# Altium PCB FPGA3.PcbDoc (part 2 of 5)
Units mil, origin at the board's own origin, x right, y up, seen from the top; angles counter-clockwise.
Board outline 4000 x 2750 mil, 12 copper layers (Top Layer, Plane1, MidLayer1, Plane2, MidLayer2, Plane3, Plane4, MidLayer 3, Plane5, MidLayer 4, Plane6, Bottom Layer), stack 57.29 mil thick; 420 components, 368 nets, 1889 pads, 1236 vias.
Unrouted connection lines stored in the file: 1.
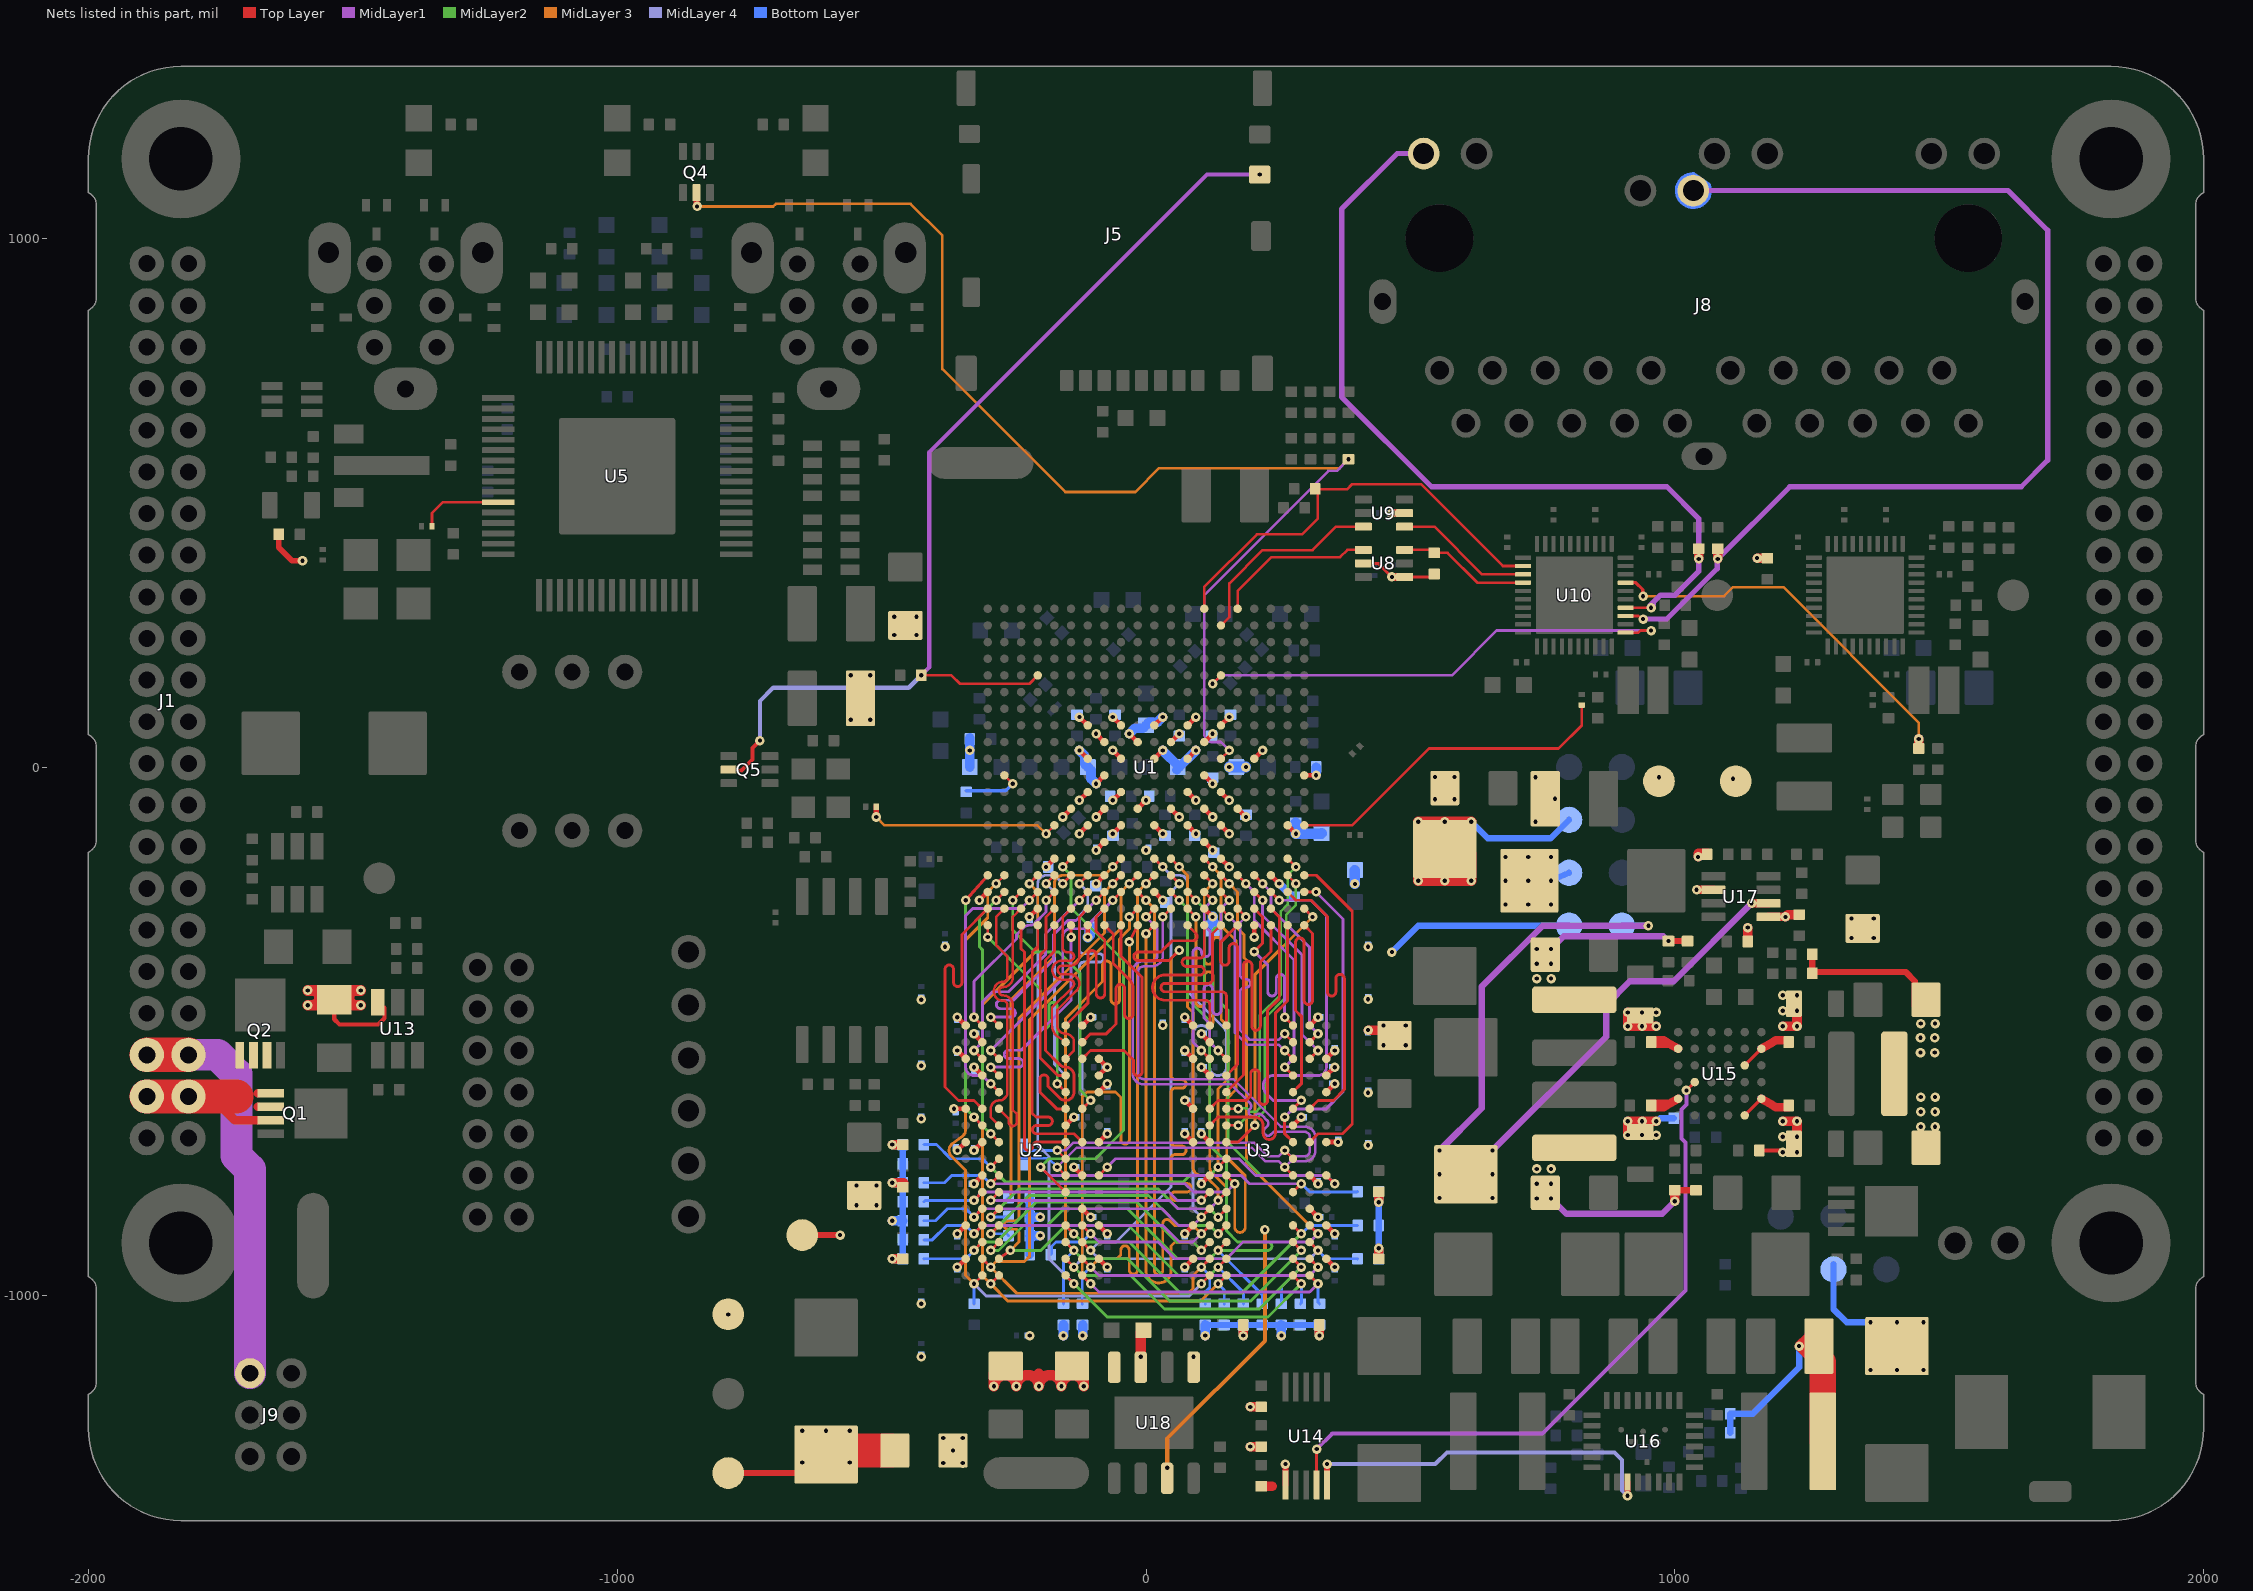
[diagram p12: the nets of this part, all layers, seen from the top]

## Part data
C1 C2 C3 C4 C5 C10 C21 C23 C24: library part CAP
C6 C7 C8 C9 C11 C12 C13 C14 C15 C16 C17 C18 C19 C20 C22 C25 C26 C27 C28 C29 C30 C31 C32 C33 C34 C35 C36 C37 C38 C39 C40 C41 C42 C43 C44 C45 C46 C47 C48 C49 C50 C51 C52 C53 C54 C55 C56 C57 C58 C59 C60 C61 C62 C63 C64 C65 C66 C67 C77 C78 CB1 CB2 CB3 CB4 CB5 CB6 CB7 CB8 CB9 CB10 CB11 CB12 CB13 CB14 CB15 CB16 CB17 CB18 CB19 CB20 CB21 CB22 CB23 CB24 CB25 CB26 CB27 CB28 CB29 CB30 CB31 CB32 CB33 CB34 CB35 CB36 CB37 CB38 CB39 CB40 CB41 CB42 CB43 CB44 CB45 CB46 CB47 CB48 CB49 CB50 CB51 CB52 CB53 CB54 CB55 CB56 CB57 CB58 CB59 CB60 CB61 CB62 CB63 CB64 CB65 CB66 CB67 CB68 CB69 CB70 CB71 CB72 CB73 CB74 CB75 CB76 CB77 CB78 CB79 CB80 CB81 CB82 CB83 CB84 CB85 CB86 CB87 CB88 CB89 CB90 CB91 CB92 CB93 CB94 CB95 CB96 CB97 CB98 CB99 CB100 CB101 CB102 CB103 CB104 CB105 CB106 CB107 CB108 CB109 CB110 CB111 CB112 CB113 CB114 CB115 CB116 CB117 CB118 CB119 CB120 CB121 CB122 CB123 CB124 CB125 CB126 CB127 CB128 CB129 CB130 CB131 CB132 CB133 CB134 CB135 CB136 CB137 CB138 CB139 CB140: library part CAP-GND
C68 C69: library part CAP-POL-GND, Voltage=50V
C70 C71: library part CAP-POL-GND, Voltage=10V
C72 C73: library part CAP-POL-GND, Volts=6.3V
C74 C75 C76: library part CAP-POL-GND, Voltage=2.5V
D1: library part TVS-GND
D2 D3 D4: Color=GREEN
D5 D6 D7 D8 D9 D10 D11 D12: library part DIODE-2/SER
J5: library part CONN-MICROSD-ST12S0
J8: "PULSE JXD0-2015NL"
L1 L2 L3 L4 L5 L6 L7 L8 L11 L12 L13 L14 L15 L16: library part INDUCTOR
M1 M2 M3 M4: "Mounting Hole"
Q1 Q2: library part MOSFET-N-PPACK
Q3: library part MOSFET-P-PPACK
Q4 Q5: library part MOSFET-N-DUAL6
Q6: library part PNP-SM
R1 R2 R3 R4 R5 R6 R7 R8 R9 R10 R11 R12 R13 R14 R15 R16 R17 R18 R19 R20 R21 R22 R23 R24 R25 R26 R27 R28 R29 R30 R31 R32 R34 R35 R38 R39 R41 R43 R46 R47 R48 R49 R50 R51 R52 R53 R54 R55 R60 R61 R62 R63 R64 R67 R68 R69 R70 R71 R72 R74 R78 R80 R84 R85 R86 R87 R88 R89 R90 R91 R94 R95 R98 R100 R102 R103 R104 R107 R108: library part R
R33 R40 R42 R44 R45 R58 R59 R60A R65 R66 R73 R75 R76 R77 R81 R82 R83 R92 R96 R97 R99 R101 R105 R106: library part R-GND
R36 R37 R56 R57 R79 R93 R109 R110 R111 R112 R113 R114 R115 R116: library part R-MINI
R117: library part R, Power=1/4W
R118: library part R, Package=1206, Power=1/4W
RN1 RN2: library part RN-DISC-SM-4X
U5: "IEEE 1394a-2000 Two-port Transceiver/Arbiter"
U6: library part TLVH431-SC70
U7: library part OSCILATOR, Freq=24.576MHz
U9: library part 2G17-1, "NC7WZ17"
U10 U11: "Ethernet PHY"
U17: library part LTC2908-B1-SOT
U19 U20: library part OSCILATOR

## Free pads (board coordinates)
  oval 60x200 smd paste-99999: 0(-1575,-905)
  round 60 smd paste-99999: 0(-1450,-210) 0(-790,-1335) 0(-790,-1185) 0(-790,-1035) 0(-650,-885) 0(970,-27) 0(1080,325) 0(1115,-27) 0(1640,325)
  oval 200x60 smd paste-99999: 0(-312.5,575) 0(-207.5,-1335)
  rrect50% 80x40 smd paste-100: 0(1710,-1370)

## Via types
v1: diameter 18, hole 8, Top Layer to Bottom Layer, tented both sides, 1236 vias

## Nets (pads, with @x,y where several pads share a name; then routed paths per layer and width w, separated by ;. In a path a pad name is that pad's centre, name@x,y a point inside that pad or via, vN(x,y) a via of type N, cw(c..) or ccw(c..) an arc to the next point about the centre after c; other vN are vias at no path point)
0.75V: C48.1 C49.1 C51.1 CB1.1 CB2.1 CB3.1 CB4.1 CB5.1 CB6.1 CB7.1 CB8.1 CB9.1 CB10.1 CB11.1 CB12.1 CB63.1 CB64.1 CB65.1 CB66.1 CB67.1 CB68.1 CB69.1 CB77.1 CB109.1 CB110.1 CB111.1 CB112.1 CB113.1 CB114.1 CB115.1 pad.0@-650,-885 R10.2 R11.2 R12.2 R13.2 R14.2 R15.2 R16.2 R17.2 R18.2 R19.2 R20.2 R21.2 R22.2 R23.2 R24.2 R25.2 R26.2 R27.2 R28.2 R29.2 R30.2 R31.2 R32.2 TP14.1 U1.H6 U1.P6 U2.H1 U2.M8 U3.H1 U3.M8 U18.3 U18.8 | length 2504.5
  Top Layer w9: v1(-356.68,-724.95) U2.H1@-340.98,-709.25 U2.H1@-340.94,-709.2 ; U2.M8@-120.51,-835.24 v1(-104.76,-850.98) ; v1(-94.49,-157.48) U1.H6@-78.74,-141.73 ; v1(73.27,-693.5) U3.H1@89.02,-709.25 ; U1.P6@110.24,-141.73 v1(125.98,-157.48) ; U3.M8@309.49,-835.24 v1(325.24,-850.98)
  Top Layer w12: pad.0@-650,-885 v1(-578.51,-885)
  Top Layer w18: v1(-480,-929.97) CB111.1@-460,-930 ; v1(-480,-785.97) CB109.1@-458,-785.97 ; v1(-480,-713.97) CB110.1@-460,-714 ; v1(183.97,-1074.97) CB115.1@184,-1055 ; v1(327.97,-1074.97) CB114.1@328,-1055 ; v1(420,-497.5) C51.1@449,-497.5 ; CB112.1@440,-930.04 v1(440.03,-910.04) ; v1@440,-822.91 CB113.1@440,-802.91
  Top Layer w20: C48.1@-287.5,-1147 v1@-287.5,-1170.93 ; -202.5,-1147 v1@-202.5,-1170.93 ; C49.1@-117.5,-1147 v1(-117.5,-1171) ccw(c-138.75,-1171) v1(-160,-1171) ccw(c-181.25,-1171) v1@-202.5,-1170.93 ; v1@-287.5,-1170.93 cw(c-266.25,-1171) v1(-245,-1171) cw(c-223.75,-1171) v1@-202.5,-1170.93 ; v1@-287.5,-1170.93 ccw(c-266.25,-1171) v1(-287.5,-1171) v1@-287.5,-1170.93 ; v1(-202.5,-1171) ccw(c-223.75,-1171) v1@-202.5,-1170.93 ; v1(-202.5,-1171) cw(c-181.25,-1171) v1@-202.5,-1170.93 ; v1(-202.5,-1171) v1@-202.5,-1170.93
  MidLayer 3 w8: v1(40,-1325) 40,-1270 225,-1085 v1(225,-875)
  Bottom Layer w12: R32.2@-460,-930 R31.2@-460,-894 R30.2@-460,-858 R29.2@-460,-822 R28.2@-460,-786 R27.2@-460,-750 R26.2@-460,-714 ; R19.2@112,-1055 R14.2@292,-1055 R13.2@328,-1055 ; v1(440.03,-910.04) v1(439.97,-822.97) ; v1(465,-350) 515,-300 TP14.1@800,-300
  Bottom Layer w16: R25.2@-220,-922 R24.2@-220,-886 -220,-850.98 R23.2@-220,-850 R22.2@-220,-814
  Bottom Layer w18: v1(-480,-929.97) R32.2@-460,-930 ; v1(-480,-857.97) R30.2@-460,-858 ; v1(-480,-785.97) R28.2@-460,-786 ; v1(-480,-713.97) R26.2@-460,-714 ; R24.2@-220,-886 v1(-200.04,-886.04) ; R23.2@-220,-850.98 v1(-200.04,-850.98) ; v1(-156.03,-1074.97) R21.2@-156,-1055 ; v1(-120.03,-1074.97) R20.2@-120,-1055 ; v1(111.97,-1074.97) R19.2@112,-1055 ; v1(183.97,-1074.97) R17.2@184,-1055 ; v1(255.97,-1074.97) R15.2@256,-1055 ; v1(327.97,-1074.97) R13.2@328,-1055 ; R12.2@440,-930 v1(440.03,-910.04) ; v1(439.97,-822.97) R10.2@440,-803
  other v1: -425,-1115 -220,-1075 -425,-1015 420,-715 -425,-665 420,-616 -425,-565 449,-526 491,-526 449,-489 491,-489 31.5,-488.19 -425,-440 420,-439 -380,-340 420,-340 0,-157.48
1.0V: C2.1 C46.1 C50.1 C52.1 C54.1 C56.1 C75.1 CB76.1 CB78.1 CB79.1 CB81.1 CB82.1 CB84.1 CB85.1 CB86.1 CB119.1 CB120.1 CB121.1 L3.2 pad.0@1115,-27 R98.1 R100.1 TP10.1 U1.G7 U1.G11 U1.G13 U1.H10 U1.H12 U1.J7 U1.J13 U1.K12 U1.L7 U1.L13 U1.M12 U1.N7 U1.N13 U1.P8 U1.P12 U1.R7 U1.R13 | length 1400.5
  Top Layer w9: v1(-125.98,-125.98) U1.G7@-110.24,-110.24 ; v1(-125.98,31.5) U1.G11@-110.24,15.75 ; v1(-125.98,94.49) U1.G13@-110.24,78.74 ; v1(-94.49,-31.5) U1.H10@-78.74,-15.75 ; v1(-94.49,62.99) U1.H12@-78.74,47.24 ; v1(-62.99,-125.98) U1.J7@-47.24,-110.24 ; v1(-62.99,94.49) U1.J13@-47.24,78.74 ; v1(-31.5,62.99) U1.K12@-15.75,47.24 ; U1.L7@15.75,-110.24 v1(31.5,-125.98) ; U1.L13@15.75,78.74 v1(31.5,94.49) ; U1.M12@47.24,47.24 v1(62.99,62.99) ; U1.N7@78.74,-110.24 v1(94.49,-125.98) ; U1.N13@78.74,78.74 v1(94.49,94.49) ; U1.P8@110.24,-78.74 v1(125.98,-94.49) ; U1.P12@110.24,47.24 v1(125.98,62.99) ; U1.R7@141.73,-110.24 v1(157.48,-125.98) ; U1.R13@141.73,78.74 v1(157.48,94.49)
  Top Layer w12: C2.1@1257.38,-387.65 C2.1@1259.88,-387.65 ; C2.1@1259.88,-390.15 C2.1@1259.88,-387.65 ; R100.1@1259.88,-354.15 C2.1@1259.88,-387.65 ; C54.1@1453.88,-450.15 1453.88,-405.15 1436.38,-387.65 C2.1@1259.88,-387.65
  Top Layer w18: v1(1044,-170) v1@1044,-167 ; R98.1@1061,-167 v1@1044,-167 ; R98.1@1061,-163 1044,-163 1044,-165 v1@1044,-167
  Top Layer w20: C75.1@515,-165 v1(515,-215) v1(565,-215) v1(615,-215) C75.1@615,-165 ; v1(515,-103.5) v1(565,-103.5) v1(615,-103.5)
  Bottom Layer w12: v1(615,-103.5) 646.5,-135 765,-135 TP10.1@800,-100
  Bottom Layer w18: v1(-125.98,31.5) -116,21.51 -116,6 CB121.1@-110,0 -104,-6 -104,-21.98 v1(-94.49,-31.5) ; v1(-31.5,62.99) -21.49,73 -6,73 CB119.1@0,79 6,85 22.01,85 v1(31.5,94.49)
  Bottom Layer w20: v1(157.48,0) v1(188.98,0)
  other v1: 1465,-680 1492,-680 1465,-652 1492,-652 1465,-624 1492,-624 1464.5,-540 1491.5,-540 1464.5,-512 1491.5,-512 1465,-485 1492,-485 1334,-323.5 1376,-323.5 1334,-286.5 1376,-286.5 546.5,-61 583.5,-61 1110,-22 546.5,-19 583.5,-19 -476,249.5 -434,249.5 -476,284 -434,284
1.2MHz_10: U14.5 U16.3 | length 710.4
  Top Layer w11: U14.5@342.37,-1357.5 v1(342.37,-1318) ; v1(910.47,-1378) U16.3@910.47,-1352
  MidLayer 4 w8: v1(342.37,-1318) 547,-1318 569,-1296 886,-1296 900.26,-1310.26 900.26,-1367.79 v1(910.47,-1378)
1.5V: C3.1 C47.1 C55.1 C76.1 CB13.1 CB14.1 CB15.1 CB16.1 CB17.1 CB18.1 CB19.1 CB20.1 CB21.1 CB22.1 CB23.1 CB24.1 CB25.1 CB26.1 CB27.1 CB28.1 CB29.1 CB30.1 CB31.1 CB32.1 CB33.1 CB34.1 CB35.1 CB36.1 CB37.1 CB38.1 CB39.1 CB40.1 CB41.1 CB42.1 CB43.1 CB44.1 CB45.1 CB46.1 CB47.1 CB48.1 CB87.1 CB95.1 CB99.1 CB103.1 CB122.1 CB133.1 L4.2 pad.0@-790,-1035 R34.1 R107.1 TP13.1 U1.A3 U1.D2 U1.E5 U1.G1 U1.H4 U1.L3 U1.P2 U1.R5 U1.U1 U1.V4 U2.A1 U2.A8 U2.B2 U2.C1 U2.C9 U2.D2 U2.D9 U2.E9 U2.F1 U2.G7 U2.H2 U2.H9 U2.K2 U2.K8 U2.N1 U2.N9 U2.R1 U2.R9 U3.A1 U3.A8 U3.B2 U3.C1 U3.C9 U3.D2 U3.D9 U3.E9 U3.F1 U3.G7 U3.H2 U3.H9 U3.K2 U3.K8 U3.N1 U3.N9 U3.R1 U3.R9 U17.2 U18.5 U18.7 | length 2996.5
  Top Layer w9: v1(-363.26,-646.26) U2.F1@-340.98,-646.26 ; v1(-356.73,-945.47) U2.R1@-340.98,-929.72 ; v1(-356.73,-882.48) U2.N1@-340.98,-866.73 ; v1(-356.73,-536.02) U2.C1@-340.98,-551.77 ; v1(-356.73,-473.03) U2.A1@-340.98,-488.78 ; v1(-325.24,-787.99) U2.K2@-309.49,-772.24 ; v1(-325.24,-725) U2.H2@-309.49,-709.25 ; v1(-325.24,-567.52) U2.D2@-309.49,-583.27 ; v1(-325.24,-504.53) U2.B2@-309.49,-520.28 ; v1(-314.96,-251.97) U1.A3@-299.21,-236.22 ; v1(-220.47,-283.46) U1.D2@-204.72,-267.72 ; v1(-188.98,-188.98) U1.E5@-173.23,-173.23 ; U2.G7@-152.01,-677.76 v1(-136.26,-662.01) ; v1(-136.26,-756.5) U2.K8@-120.51,-772.24 ; U2.A8@-120.51,-488.78 v1(-104.76,-473.03) ; v1(-110.24,-321.48) U1.G1@-110.24,-299.21 ; v1(-94.49,-220.47) U1.H4@-78.74,-204.72 ; U2.R9@-89.02,-929.72 v1(-73.27,-945.47) ; U2.N9@-89.02,-866.73 v1(-73.27,-882.48) ; U2.H9@-89.02,-709.25 v1(-73.27,-693.5) ; U2.E9@-89.02,-614.76 v1(-73.27,-599.02) ; U2.D9@-89.02,-583.27 v1(-73.27,-567.52) U2.C9@-89.02,-551.77 ; U1.L3@15.75,-236.22 v1(31.5,-251.97) ; v1(73.27,-945.47) U3.R1@89.02,-929.72 ; v1(73.27,-882.48) U3.N1@89.02,-866.73 ; v1(73.27,-630.51) U3.F1@89.02,-646.26 ; v1(73.27,-536.02) U3.C1@89.02,-551.77 ; v1(73.27,-473.03) U3.A1@89.02,-488.78 ; v1(104.76,-787.99) U3.K2@120.51,-772.24 ; v1(104.76,-693.5) U3.H2@120.51,-709.25 ; v1(104.76,-567.52) U3.D2@120.51,-583.27 ; v1(104.76,-504.53) U3.B2@120.51,-520.28 ; U1.P2@110.24,-267.72 v1(125.98,-283.46) ; U1.R5@141.73,-173.23 v1(157.48,-188.98) ; v1(204.72,-321.48) U1.U1@204.72,-299.21 ; U1.V4@236.22,-204.72 v1(251.97,-220.47) ; U3.G7@277.99,-677.76 v1(293.74,-662.01) ; U3.K8@309.49,-772.24 v1(325.24,-787.99) ; U3.A8@309.49,-488.78 v1(325.24,-473.03) ; U3.R9@340.98,-929.72 v1(356.73,-945.47) ; U3.N9@340.98,-866.73 v1(356.73,-882.48) ; U3.H9@340.98,-709.25 v1(363.26,-709.25) ; U3.E9@340.98,-614.76 v1(356.73,-599.02) ; U3.D9@340.98,-583.27 v1(356.73,-567.52) ; U3.C9@340.98,-551.77 v1(356.73,-536.02)
  Top Layer w12: C3.1@1000,-800 R107.1@1040,-800
  Top Layer w16: v1(1145,-257.8) U17.2@1177,-257.8
  Top Layer w18: v1(1000,-821) C3.1@1000,-800
  Top Layer w20: U18.7@-10,-1135 v1(-10,-1115) -10,-1070 CB133.1@-5,-1065
  MidLayer1 w12: v1(555,-725) 635,-645 635,-415 750,-300 v1(950,-300) ; v1(655,-725) 870,-510 870,-450 915,-405 997.8,-405 v1(1145,-257.8) ; v1(766,-816) 795,-845 976,-845 v1(1000,-821)
  Bottom Layer w12: TP13.1@900,-300 v1(950,-300)
  Bottom Layer w15: v1(251.97,-220.47) CB95.1@277.42,-245.93
  Bottom Layer w20: v1(-110.24,-321.48) -106.61,-317.86 CB99.1@-106.61,-302.5 ; CB122.1@125.98,-303.5 v1(125.98,-283.46)
  other v1: 90,-1115 -790,-1035 -547.5,-828.5 -509.5,-828.5 739,-816 555,-815 655,-815 -547.5,-791.5 -509.5,-791.5 739,-788 766,-788 555,-770 655,-770 739,-760 766,-760
1.8V: C1.1 C53.1 C66.1 C67.1 C74.1 CB70.1 CB71.1 CB80.1 CB83.1 CB93.1 CB98.1 CB102.1 CB106.1 CB107.1 CB118.1 CB127.1 CB128.1 L5.2 L8.1 pad.0@970,-27 R62.2 R63.2 R108.1 TP12.1 U1.F8 U1.G9 U1.H8 U1.J9 U1.J11 U1.K8 U1.L11 U1.M8 U1.N9 U1.N11 U1.P10 U1.R9 U1.T8 U1.U11 U1.W7 U1.Y10 U8.1 U8.5 U9.5 U17.6 | length 1182.8
  Top Layer w5: U8.1@489,359.41 R62.2@539.41,359.41
  Top Layer w6: U8.5@411,385 439.41,385 v1(465,359.41)
  Top Layer w8: C66.1@-540,130 -540,136.5 C66.1@-516.5,160
  Top Layer w9: v1(-157.48,-94.49) U1.F8@-141.73,-78.74 ; v1(-125.98,-62.99) U1.G9@-110.24,-47.24 ; v1(-94.49,-94.49) U1.H8@-78.74,-78.74 ; v1(-62.99,-62.99) U1.J9@-47.24,-47.24 ; v1(-62.99,31.5) U1.J11@-47.24,15.75 ; U1.K8@-15.75,-78.74 v1(0,-62.99) ; U1.L11@15.75,15.75 v1(31.5,31.5) ; U1.M8@47.24,-78.74 v1(62.99,-94.49) ; U1.N9@78.74,-47.24 v1(94.49,-62.99) ; U1.N11@78.74,15.75 v1(94.49,31.5) ; U1.P10@110.24,-15.75 v1(125.98,-31.5) ; U1.R9@141.73,-47.24 v1(157.48,-62.99) ; U1.T8@173.23,-78.74 v1(188.98,-94.49) ; U1.U11@204.72,15.75 v1(220.47,31.5) ; U1.W7@267.72,-110.24 v1(283.47,-125.98) ; U1.Y10@299.21,-15.75 v1(321.48,-15.75)
  Top Layer w12: v1(988,-329) R108.1@1024,-329
  Top Layer w15: v1(465,359.41) U8.1@489,359.41 ; v1(465,480) U9.5@489,480
  Top Layer w16: v1(1041,-232.2) U17.6@1073,-232.2
  Top Layer w18: v1(1155.5,395) R63.2@1175,395
  MidLayer1 w12: v1(766,-344) 790,-320 977.97,-320 986.97,-329 v1(988,-329)
  Bottom Layer w12: v1(766,-215) TP12.1@800,-200
  Bottom Layer w18: L8.1@-333.15,0 CB102.1@-333.15,55 ; v1@31.5,31.4 CB118.1@63.32,-0.42 ; CB118.1@58.06,-4.83 94.39,31.5 v1(94.49,31.5) ; v1(321.48,-15.75) 321.48,-0.52 CB98.1@322,0
  Bottom Layer w20: CB93.1@283.46,-105 v1(283.47,-125.98) 331.02,-125.98 CB127.1@332,-125 ; v1(395,-221) CB128.1@395,-195
  other v1: 739,-400 766,-400 739,-372 766,-372 739,-344 680,-260 723,-260 766,-260 680,-215 723,-215 680,-170 723,-170 766,-170 736.5,-103.5 773.5,-60 736.5,-19.5 970,-19.5 -333.15,31.5 -558.5,89.5 -521.5,89.5 -558.5,173.5 -521.5,173.5
3.3V-OUT_2: J1.39 J1.40 J9.2 Q2.1 Q2.2 Q2.3 | length 839.8
  Top Layer w65: J1.40@-1889.37,-544.29 J1.39@-1810.63,-544.29
  MidLayer1 w60: J1.40@-1889.37,-544.29 J1.39@-1810.63,-544.29 -1755.71,-544.29 -1720,-580 -1720,-735 -1694.37,-760.63 J9.2@-1694.37,-1146.26
5V: C70.1 L16.2 pad.0@-790,-1335 R57.1 R118.1 U13.6 | length 871.9
  Top Layer w8: R118.1@-1535,-440 -1535,-477 -1525,-487 -1452,-487 -1440,-475 -1440,-455
  Top Layer w11: R57.1@-1640,440 -1640,415 -1615,390 v1(-1595,390) ; pad.0@-790,-1335 -640,-1335 C70.1@-605,-1300
  Top Layer w20: v1(-1585,-450.5) v1@-1577,-450.5 ; v1(-1585,-422.5) v1@-1577,-422.5 ; R118.1@-1540,-450.5 v1@-1577,-450.5 ; R118.1@-1540,-422.5 v1@-1577,-422.5 ; R118.1@-1530,-450.5 v1@-1493,-450.5 ; R118.1@-1530,-422.5 v1@-1493,-422.5 ; v1(-1485,-450.5) v1@-1493,-450.5 ; v1(-1485,-422.5) v1@-1493,-422.5 ; v1@-1577,-450.5 ccw(c-1577,-436.5) v1@-1577,-422.5 ; v1@-1577,-450.5 ccw(c-1577,-436.5) v1@-1577,-422.5 ; v1@-1493,-450.5 cw(c-1493,-436.5) v1@-1493,-422.5 ; v1@-1493,-450.5 cw(c-1493,-436.5) v1@-1493,-422.5
  Top Layer w65: C70.1@-557.5,-1292.5 L16.2@-482.5,-1292.5
  other v1: -650,-1315 -560,-1315 -650,-1255 -605,-1255 -560,-1255
5V-DCDC_10: C4.1 C15.1 C16.1 C17.1 C18.1 C19.1 C22.1 C42.1 C43.1 C44.1 C45.1 C65.1 C71.1 L1.2 L16.1 R9.2 R72.1 R74.1 R94.2 R95.2 R103.1 TP3.1 U14.1 U15.B1 U15.B6 U15.C5 U15.E1 U15.E6 U15.F5 U17.1 | length 1525.1
  Top Layer w6: U15.F5@1132.24,-658.74 U15.E6@1163.74,-627.24 ; U15.C5@1132.24,-564.25 U15.B6@1163.74,-532.76
  Top Layer w8: R72.1@1160,-725 1203,-725 v1@1204,-726
  Top Layer w11: U14.1@263.63,-1357.5 v1(263.63,-1318)
  Top Layer w12: U17.1@1176.43,-283.95 U17.1@1177,-283.39
  Top Layer w16: C17.1@955,-643 978.97,-643 989.36,-637 ; C17.1@955,-637 989.36,-637 ; C16.1@955,-523 989.36,-523 ; C16.1@955,-517 978.97,-517 989.36,-523 ; U15.E1@1006.26,-627.24 989.36,-637 ; U15.B1@1006.26,-532.76 989.36,-523 ; U15.E6@1163.74,-627.24 1180.64,-637 1191.03,-643 C19.1@1215,-643 ; U15.B6@1163.74,-532.76 1180.64,-523 1191.03,-517 C18.1@1215,-517 ; U17.1@1177,-283.39 v1(1209,-283.39)
  Top Layer w18: v1(197,-1285) R95.2@218,-1285 ; v1(197,-1210) R94.2@218,-1210 ; C22.1@218,-1360 239,-1360 ; v1(911,-696) v1(911,-670) v1(938,-670) v1(965,-670) ; v1(911,-464) v1(911,-490) v1(938,-490) v1(965,-490) ; R9.2@1138,-330 v1(1138,-303.5) ; v1(1204,-670) v1(1231,-670) C45.1@1231,-697 ; v1(1204,-490) v1(1231,-490) C43.1@1231,-463 ; v1(1209,-283.39) 1213.04,-279.35 1234.65,-279.35 C15.1@1235,-279 ; C65.1@1252.68,-1112.68 v1(1235,-1095) C65.1@1252.68,-1077.32
  Top Layer w50: L1.2@1280,-1275 C65.1@1280,-1125
  Bottom Layer w12: v1(965,-670) 966.62,-670 972.62,-664 R74.1@998,-664 ; R103.1@1105,-1259 C4.1@1105,-1223 1147,-1223 1235,-1135 v1(1235,-1095) ; TP3.1@1300,-940 TP3.1@1300,-950 1300,-1025 1325,-1050 v1(1370,-1050)
  other v1: -383.5,-1316 -346.5,-1316.07 -365,-1292.57 -383.5,-1269 -346.5,-1269 1370,-1140 1420,-1140 1470,-1140 1420,-1050 1470,-1050 1204,-728.5 1231,-728.5 1204,-699 1231,-699 938,-696 965,-696 938,-464 965,-464 1204,-461 1231,-461 1204,-431.5 1231,-431.5
5V-OUT_2: J1.41 J1.42 Q1.1 Q1.2 Q1.3 | length 283.2
  Top Layer w16: -1767.78,-623.03 -1723.02,-667.8 -1680,-667.8 Q1.3@-1677.5,-667.8 ; Q1.2@-1680,-642.2 Q1.2@-1677.5,-642.2 ; Q1.1@-1680,-616.61 Q1.1@-1677.5,-616.61
  Top Layer w65: J1.42@-1889.37,-623.03 J1.41@-1810.63,-623.03 -1767.78,-623.03 -1720,-623.03
/1.2MHz_10: U14.4 U15.D2 | length 1297.1
  Top Layer w6: U14.4@322.68,-1357.5 v1(322.68,-1289.68) ; v1(1022.01,-611.5) U15.D2@1037.76,-595.75
  MidLayer1 w8: v1(322.68,-1289.68) 352.37,-1260 750,-1260 1020,-990 1020,-710 1012.5,-702.5 1012.5,-647.5 1022.01,-637.99 v1(1022.01,-611.5)
/CAS_7: R28.1 U1.P5 U2.K3 U3.K3 | length 1514.1
  Top Layer w5.49: v1(-293.74,-787.99) U2.K3@-277.99,-772.24 ; U1.P5@110.24,-173.23 v1(125.98,-188.98) ; U3.K3@152.01,-772.24 v1(167.76,-787.99)
  MidLayer1 w5.49: v1(-293.74,-787.99) 73.88,-787.99 89.63,-803.74 152.01,-803.74 v1(167.76,-787.99)
  MidLayer 3 w5.49: v1(125.98,-188.98) 141.73,-204.72 141.73,-300 170,-328.27 170,-610 152.76,-627.24 152.76,-737.76 187.76,-772.76 187.76,-870 cw(c177.76,-870) 167.76,-870 v1(167.76,-787.99)
  Bottom Layer w5.49: R28.1@-420,-786 -381,-786 -367.24,-772.24 -309.49,-772.24 v1@-293.77,-787.96
/CS_7: R29.1 U1.N1 U2.L2 U3.L2 | length 1532.2
  Top Layer w5.49: v1(-325.24,-819.49) U2.L2@-309.49,-803.74 ; v1(62.99,-346.46) 43.45,-366 -15,-366 cw(c-15,-358) -15,-350 27.95,-350 49.45,-328.5 88.71,-328.5 ccw(c88.71,-320.5) 94.37,-314.84 U1.N1@78.74,-299.21 ; v1(104.76,-819.49) U3.L2@120.51,-803.74
  MidLayer1 w5.49: v1(-325.24,-819.49) -309.49,-803.74 43.74,-803.74 59.49,-819.49 v1(104.76,-819.49)
  MidLayer 3 w5.49: v1(62.99,-346.46) 47.24,-362.21 47.24,-583 ccw(c55.24,-583) 55.24,-591 67.77,-591 cw(c67.77,-599) 67.77,-607 55.24,-607 ccw(c55.24,-615) 47.24,-615 47.24,-708.8 ccw(c55.24,-708.8) 55.24,-716.8 67.77,-716.8 cw(c67.77,-724.8) 67.77,-732.8 55,-732.8 ccw(c55,-740.8) 47,-740.8 47,-779.49 ccw(c55,-779.49) 55,-787.49 77.5,-787.49 cw(c77.5,-795.49) 77.5,-803.49 55,-803.49 ccw(c55,-811.49) 55,-819.49 v1(104.76,-819.49)
  Bottom Layer w5.49: R29.1@-420,-822 -417.48,-819.49 v1(-325.24,-819.49)
/RAS_7: R26.1 U1.P4 U2.J3 U3.J3 | length 1340.1
  Top Layer w5.49: v1(-293.74,-756.5) U2.J3@-277.99,-740.75 ; U1.P4@110.24,-204.72 v1(125.98,-220.47) ; v1@136.36,-756.5 152.06,-740.8 U3.J3@152.1,-740.75
  MidLayer2 w5.49: v1(-293.74,-756.5) -265.23,-785 70,-785 82.76,-772.24 120.51,-772.24 v1(136.26,-756.5)
  MidLayer 3 w5.49: v1(125.98,-220.47) 110.24,-236.22 110.24,-365 ccw(c118.24,-365) 126.24,-365 126.24,-330 cw(c134.24,-330) 142.24,-330 142.24,-477.24 155,-490 155,-590 136.26,-608.74 136.26,-756.4 v1@136.36,-756.5
  Bottom Layer w5.49: R26.1@-420,-714 -396,-714 -369.25,-740.75 -309.49,-740.75 v1@-293.77,-756.47
/RESET_6: R55.1 U1.B10 | length 115.9
  Top Layer w5: U1.B10@-267.72,-15.75 v1(-251.97,-31.5)
  Bottom Layer w6: R55.1@-340,-45 -265.47,-45 v1(-251.97,-31.5)
/RESET_7: R75.1 U1.B4 U2.T2 U3.T2 | length 1369.9
  Top Layer w5: v1(-325.24,-976.97) U2.T2@-309.49,-961.22 ; v1(-283.46,-220.47) U1.B4@-267.72,-204.72 ; v1(104.76,-976.97) U3.T2@120.51,-961.22
  MidLayer1 w6: v1@-325.24,-980.22 v1(-325.24,-976.97)
  MidLayer 3 w5.49: v1(-325.24,-976.97) -340.98,-961.22 -340.98,-762.92 -367.82,-736.09 cw(c-356.68,-724.95) -366.38,-712.54 -347.03,-697.91 ccw(c-356.73,-685.5) -340.98,-685.5 -340.98,-326.77 -299.21,-285 -299.21,-236.22 v1(-283.46,-220.47)
  MidLayer 4 w5.49: v1(-325.24,-976.97) -302.2,-1000 81.73,-1000 v1(104.76,-976.97)
  Bottom Layer w6: v1(-325.24,-976.97) -325.24,-1014.76 R75.1@-325,-1015
/SD-CD: J5.11 Q5.5 R53.1 U1.D16 | length 2003.4
  Top Layer w5: v1(-425,173.5) -368.03,173.5 -352.01,157.48 -220.47,157.48 U1.D16@-204.72,173.23
  Top Layer w6: Q5.5@-789,-5 Q5.5@-787.5,-5
  Top Layer w8: Q5.5@-787.5,-5 -789.24,-6.74 -764.74,-6.74 -744,14 -744,36 v1(-730,50)
  MidLayer1 w8: v1(-425,173.5) -410,188.5 -410,595 115.28,1120.28 v1(215,1120.28)
  MidLayer 4 w8: v1(-730,50) -730,125 -705,150 -448.5,150 v1(-425,173.5)
/WE_7: R22.1 U1.M5 U2.L3 U3.L3 | length 1212.3
  Top Layer w5.49: v1(-293.74,-819.49) U2.L3@-277.99,-803.74 ; U1.M5@47.24,-173.23 v1(62.99,-188.98) ; v1(136.26,-819.49) U3.L3@152.01,-803.74
  MidLayer1 w5.49: v1(-293.74,-819.49) 44.49,-819.49 60.24,-835.24 120.51,-835.24 v1(136.26,-819.49)
  MidLayer 3 w5.49: v1(62.99,-188.98) 78.74,-204.72 78.74,-453.74 89.02,-464.02 89.02,-756.5 ccw(c104.76,-756.5) 104.76,-772.24 cw(c104.76,-787.99) 115.9,-776.86 136.26,-797.22 v1(136.26,-819.49)
  Bottom Layer w5: v1(-293.74,-819.49) -265.48,-819.49 R22.1@-260,-814
A0: R24.1 U1.N2 U2.N3 U3.N3 | length 1362.7
  Top Layer w5.49: v1(-293.74,-882.48) U2.N3@-277.99,-866.73 ; U1.N2@78.74,-267.72 v1(94.49,-283.46) ; v1(136.26,-882.48) U3.N3@152.01,-866.73
  MidLayer2 w5.49: v1(-293.74,-882.48) -221.26,-810 5,-810 61.73,-866.73 120.51,-866.73 v1(136.26,-882.48)
  MidLayer 3 w5.49: v1(94.49,-283.46) 94.49,-445 ccw(c102.49,-445) 110.49,-445 110.49,-395 cw(c118.49,-395) 126.49,-395 126.49,-483.51 120.51,-489.49 120.51,-756.5 ccw(c136.26,-756.5) 125.12,-767.63 152.01,-794.52 152.01,-866.73 v1(136.26,-882.48)
  Bottom Layer w5: v1(-293.74,-882.48) -263.52,-882.48 R24.1@-260,-886
A1: R21.1 U1.K2 U2.P7 U3.P7 | length 1539.5
  Top Layer w5.49: U2.P7@-152.01,-898.23 v1(-136.26,-913.98) ; v1(-31.5,-283.46) U1.K2@-15.75,-267.72 ; U3.P7@277.99,-898.23 v1(293.74,-913.98)
  MidLayer2 w5.49: v1(-136.26,-913.98) -120.51,-929.72 -35,-929.72 45.28,-1010 197.72,-1010 v1(293.74,-913.98)
  MidLayer 3 w5.49: v1(-136.26,-913.98) -152.01,-898.23 -152.01,-475.8 -82,-405.79 -82,-375 cw(c-74,-375) -66,-375 -66,-440 ccw(c-58,-440) -50,-440 -50,-325 -31.5,-306.5 v1(-31.5,-283.46)
  Bottom Layer w5.49: R21.1@-156,-1015 -156,-933.72 v1(-136.26,-913.98)
A2: R16.1 U1.M3 U2.P3 U3.P3 | length 1578.3
  Top Layer w5.49: v1(-293.74,-913.98) U2.P3@-277.99,-898.23 ; U1.M3@47.24,-236.22 v1(62.99,-251.97) ; v1(136.26,-913.98) U3.P3@152.01,-898.23
  MidLayer2 w5.49: v1(-293.74,-913.98) -278.98,-913.98 -231.73,-866.73 -186.73,-866.73 -155.24,-835.24 -34.76,-835.24 59.72,-929.72 120.51,-929.72 v1(136.26,-913.98) 230,-913.98 ccw(c230,-905.98) 230,-897.98 172.98,-897.98 152.01,-877.01 152.01,-747.01 120.51,-715.51 120.51,-480.51 78.74,-438.74 78.74,-267.72 v1(62.99,-251.97)
  Bottom Layer w5.49: v1(136.26,-913.98) 220,-997.72 R16.1@220,-1015
A3: R31.1 U1.K3 U2.N2 U3.N2 | length 1544.1
  Top Layer w5.49: v1(-325.24,-882.48) U2.N2@-309.49,-866.73 ; U1.K3@-15.75,-236.22 v1(0,-251.97) ; v1(104.76,-882.48) U3.N2@120.51,-866.73
  MidLayer1 w5.49: v1(-325.24,-882.48) -309.49,-866.73 31.73,-866.73 63.23,-898.23 89.02,-898.23 v1(104.76,-882.48)
  MidLayer 3 w5.49: v1(0,-251.97) 15.75,-267.72 15.75,-952 ccw(c23.75,-952) 31.75,-952 31.75,-863.5 cw(c39.75,-863.5) 45.4,-857.85 54.29,-866.73 89.02,-866.73 v1(104.76,-882.48)
  Bottom Layer w5.49: R31.1@-420,-894 -404,-894 -376.73,-866.73 -340.99,-866.73 v1(-325.24,-882.48)
A4: R12.1 U1.M4 U2.P8 U3.P8 | length 1373.1
  Top Layer w5.49: U2.P8@-120.51,-898.23 v1(-104.76,-913.98) ; U1.M4@47.24,-204.72 v1(62.99,-220.47) ; U3.P8@309.49,-898.23 v1(325.24,-913.98)
  MidLayer 4 w5.49: v1(62.99,-220.47) 47.24,-236.22 47.24,-794.21 -56.77,-898.23 -89.02,-898.23 v1(-104.76,-913.98) -89.02,-929.72 309.49,-929.72 v1(325.24,-913.98)
  Bottom Layer w5.49: v1@325.27,-914.01 340.98,-929.72 399.72,-929.72 R12.1@400,-930
A5: R32.1 U1.L1 U2.P2 U3.P2 | length 1498.9
  Top Layer w5.49: v1(-325.24,-913.98) U2.P2@-309.49,-898.23 ; v1(0,-314.96) U1.L1@15.75,-299.21 ; v1(104.76,-913.98) U3.P2@120.51,-898.23
  MidLayer2 w5.49: v1(-325.24,-913.98) -309.49,-898.23 -283.23,-898.23 -207.5,-822.5 -17.5,-822.5 58.22,-898.23 89.02,-898.23 v1(104.76,-913.98)
  MidLayer 3 w5.49: v1(0,-314.96) 0,-952 ccw(c23.75,-952) 47.5,-952 47.5,-905.44 54.7,-898.23 89.02,-898.23 v1(104.76,-913.98)
  Bottom Layer w5.49: R32.1@-420,-930 -419.72,-929.72 -340.98,-929.72 v1@-325.27,-914.01
A6: R20.1 U1.L4 U2.R8 U3.R8 | length 1486.4
  Top Layer w5.49: U2.R8@-120.51,-929.72 v1(-104.76,-945.47) ; v1(0,-220.47) U1.L4@15.75,-204.72 ; U3.R8@309.49,-929.72 v1(325.24,-945.47)
  MidLayer1 w5.49: v1(-104.76,-945.47) -89.02,-961.22 309.49,-961.22 v1(325.24,-945.47)
  MidLayer 3 w5.49: v1(-104.76,-945.47) -89.02,-929.72 -54.72,-929.72 -47.75,-922.75 -47.75,-913.25 cw(c-39.75,-913.25) -31.75,-913.25 -31.75,-950.75 ccw(c-23.75,-950.75) -15.75,-950.75 -15.75,-236.22 v1(0,-220.47)
  Bottom Layer w5.49: R20.1@-120.51,-1015 -120.51,-961.22 v1(-104.76,-945.47)
A7: R19.1 U1.K4 U2.R2 U3.R2 | length 1465.4
  Top Layer w5.49: U2.R2@-309.58,-929.72 v1@-293.84,-945.47 ; v1(-31.5,-220.47) U1.K4@-15.75,-204.72 ; v1(104.76,-945.47) U3.R2@120.51,-929.72
  MidLayer 3 w5.49: v1(-31.5,-220.47) -47.24,-236.22 -47.24,-304.74 -220,-477.5 -220,-925 -230,-935 -283.36,-935 -293.84,-945.47 -244.31,-995 80,-995 89.02,-985.98 89.02,-961.22 v1(104.76,-945.47)
  Bottom Layer w5.49: v1(104.76,-945.47) 120.51,-961.22 120.51,-984.49 112,-993 R19.1@112,-1015
  other v1: -293.74,-945.47
A8: R13.1 U1.K1 U2.T8 U3.T8 | length 1482.4
  Top Layer w5.49: U2.T8@-120.51,-961.22 v1(-104.76,-976.97) ; v1(-31.5,-330.71) U1.K1@-15.75,-299.21 ; U3.T8@309.49,-961.22 v1(325.24,-976.97)
  MidLayer1 w5.49: v1(-104.76,-976.97) -89.02,-992.72 309.49,-992.72 v1(325.24,-976.97)
  MidLayer 3 w5.49: v1(-104.76,-976.97) -120.51,-961.22 -120.51,-623.5 -111.77,-614.76 -57.52,-614.76 -47.5,-624.79 -47.5,-705 ccw(c-39.5,-705) -31.5,-705 v1(-31.5,-330.71)
  Bottom Layer w5.49: v1(325.24,-976.97) 325.24,-1012.24 R13.1@328,-1015
A9: R17.1 U1.J4 U2.R3 U3.R3 | length 1435.8
  Top Layer w5.49: U2.R3@-277.99,-929.72 v1(-256.24,-913.98) ; v1(-62.99,-220.47) U1.J4@-47.24,-204.72 ; v1(136.26,-945.47) U3.R3@152.01,-929.72
  MidLayer2 w5.49: v1(-256.24,-913.98) -198.98,-913.98 -151.73,-866.73 -33.27,-866.73 61.22,-961.22 120.51,-961.22 v1(136.26,-945.47)
  MidLayer 3 w5.49: v1(-256.24,-913.98) -240,-897.73 -240,-882 ccw(c-248,-882) -248,-874 -260.77,-874 cw(c-260.77,-866) -260.77,-858 -248,-858 ccw(c-248,-850) -240,-850 -240,-475 -78.74,-313.74 -78.74,-236.22 v1(-62.99,-220.47)
  Bottom Layer w5.49: v1(136.26,-945.47) 184,-993.21 R17.1@184,-1015
A10: R10.1 U1.F5 U2.L7 U3.L7 | length 1461.9
  Top Layer w5.49: v1(-199.25,-756.5) U2.L7@-152.01,-803.74 ; v1(-157.48,-188.98) U1.F5@-141.73,-173.23 ; U3.L7@277.99,-803.74 v1(293.74,-787.99)
  MidLayer1 w5.49: v1(-199.25,-756.5) -183.5,-772.24 180,-772.24 195.75,-787.99 v1(293.74,-787.99)
  MidLayer2 w5.49: v1(-199.25,-756.5) -183.5,-740.75 -95.75,-740.75 -42.52,-687.52 -42.52,-365.95 -141.73,-266.73 -141.73,-204.72 v1(-157.48,-188.98)
  Bottom Layer w5.49: v1@293.77,-788.02 309.49,-803.74 399.26,-803.74 R10.1@400,-803
A11: R15.1 U1.G4 U2.R7 U3.R7 | length 1473
  Top Layer w5.49: U2.R7@-152.01,-929.72 v1(-136.26,-945.47) ; v1(-125.98,-220.47) U1.G4@-110.24,-204.72 ; U3.R7@277.99,-929.72 v1(293.74,-945.47)
  MidLayer2 w5.49: v1(-136.26,-945.47) -120.51,-961.22 -28.78,-961.22 35,-1025 214.21,-1025 v1(293.74,-945.47)
  MidLayer 4 w5.49: v1(-136.26,-945.47) -120.51,-929.72 -120.51,-550 -125.98,-544.53 -125.98,-377 cw(c-117.98,-377) -117.98,-369 -87.98,-369 ccw(c-87.98,-361) -87.98,-353 -117.98,-353 cw(c-117.98,-345) -125.98,-345 -125.98,-280.98 -110.24,-265.24 -110.24,-236.22 v1(-125.98,-220.47)
  Bottom Layer w5.49: R15.1@256,-1015 256,-983.21 v1(293.74,-945.47)
A12: R11.1 U1.E4 U2.N7 U3.N7 | length 1386.7
  Top Layer w5.49: v1(-188.98,-220.47) U1.E4@-173.23,-204.72 ; U2.N7@-152.01,-866.73 v1(-136.26,-882.48) ; U3.N7@277.99,-866.73 v1(293.74,-882.48)
  MidLayer2 w5.49: v1(-136.26,-882.48) -120.51,-898.23 -31.77,-898.23 65,-995 181.22,-995 v1(293.74,-882.48)
  MidLayer 4 w5.49: v1(-188.98,-220.47) -173.23,-236.22 -173.23,-562.05 -152.01,-583.27 -152.01,-866.73 v1(-136.26,-882.48)
  Bottom Layer w5.49: v1@293.77,-882.45 309.49,-866.73 399.73,-866.73 R11.1@400,-867
A13: R18.1 U1.D4 U2.T3 U3.T3 | length 1381.8
  Top Layer w5.49: v1(-293.74,-976.97) U2.T3@-277.99,-961.22 ; v1(-220.47,-220.47) U1.D4@-204.72,-204.72 ; v1(136.26,-976.97) U3.T3@152.01,-961.22
  MidLayer2 w5: v1@135,-978.23 v1(136.26,-976.97)
  MidLayer 3 w5.49: v1(-220.47,-220.47) -204.73,-236.22 -204.73,-344.73 -309.49,-449.49 -309.49,-961.22 v1(-293.74,-976.97) -260.71,-1010 103.23,-1010 v1(136.26,-976.97)
  Bottom Layer w5.49: v1(136.26,-976.97) 148,-988.71 R18.1@148,-1015
A14: R14.1 U1.F4 U2.T7 U3.T7 | length 1435.4
  Top Layer w5.49: v1(-157.48,-220.47) U1.F4@-141.73,-204.72 ; U2.T7@-152.01,-961.22 v1(-136.26,-976.97) ; U3.T7@277.99,-961.22 v1(293.74,-976.97)
  MidLayer2 w5.49: v1(-136.26,-976.97) -73.23,-1040 230.71,-1040 v1(293.74,-976.97)
  MidLayer 4 w5.49: v1(-157.48,-220.47) -173.23,-204.72 -188.98,-204.72 ccw(c-188.98,-220.47) -204.72,-220.47 -204.72,-715.28 -183.5,-736.5 -183.5,-929.72 v1(-136.26,-976.97)
  Bottom Layer w5.49: R14.1@292,-1015 293.74,-1013.26 v1(293.74,-976.97)
BA0_7: R30.1 U1.L5 U2.M2 U3.M2 | length 1588.1
  Top Layer w5.49: v1(-325.24,-850.98) U2.M2@-309.49,-835.24 ; U1.L5@15.75,-173.23 v1(31.5,-188.98) ; v1(104.76,-850.98) U3.M2@120.51,-835.24
  MidLayer1 w5.49: v1(-325.24,-850.98) -309.49,-835.24 30.24,-835.24 61.73,-866.73 89.02,-866.73 v1(104.76,-850.98)
  MidLayer 4 w5.49: v1(31.5,-188.98) 47.24,-204.72 62.99,-204.72 cw(c62.99,-220.47) 78.74,-220.31 ; 78.74,-220.47 ccw(c62.99,-220.47) 78.74,-220.31 ; v1(104.76,-850.98) 89.02,-835.24 89.02,-504.53 cw(c104.76,-504.53) 120.51,-504.53 120.51,-567.52 ccw(c136.26,-567.52) 152.01,-567.52 152.01,-504.53 ccw(c136.26,-504.53) 147.4,-493.39 78.74,-424.74 78.74,-220.31
  Bottom Layer w5.49: R30.1@-420,-858 -398,-858 -375.24,-835.24 -340.98,-835.24 v1@-325.27,-850.95
BA1_7: R25.1 U1.R4 U2.N8 U3.N8 | length 1367.2
  Top Layer w5.49: U2.N8@-120.51,-866.73 v1(-104.76,-882.48) ; U1.R4@141.73,-204.72 v1(157.48,-220.47) ; U3.N8@309.49,-866.73 v1(325.24,-882.48)
  MidLayer1 w5.49: v1(-104.76,-882.48) -89.02,-898.23 23.23,-898.23 54.72,-929.72 152.01,-929.72 183.5,-898.23 309.49,-898.23 v1(325.24,-882.48)
  MidLayer 3 w5.49: v1(157.48,-220.47) 173.23,-236.22 173.23,-305 185,-316.77 185,-360 190.03,-365.03 190.03,-747.27 v1(325.24,-882.48)
  Bottom Layer w5.49: R25.1@-180,-922 -178.43,-920.43 -178.43,-906.43 -170.23,-898.23 -120.51,-898.23 v1(-104.76,-882.48)
BA2_7: R23.1 U1.J5 U2.M3 U3.M3 | length 1381.6
  Top Layer w5.49: v1(-293.74,-850.98) U2.M3@-277.99,-835.24 ; v1(-62.99,-188.98) U1.J5@-47.24,-173.23 ; v1(136.26,-850.98) U3.M3@152.01,-835.24
  MidLayer2 w5.49: v1(-293.74,-850.98) -240.26,-797.5 22.5,-797.5 60.23,-835.24 120.51,-835.24 v1(136.26,-850.98)
  MidLayer 3 w5: -157.62,-204.72 cw(c-157.48,-220.47) -157.48,-204.72
  MidLayer 3 w5.49: v1(-293.74,-850.98) -255,-812.24 -255,-440 -173.23,-358.23 -173.23,-220.47 cw(c-157.48,-220.47) -157.62,-204.72 -78.74,-204.72 v1(-62.99,-188.98)
  Bottom Layer w5: v1(-293.74,-850.98) -260.98,-850.98 R23.1@-260,-850
CLK33_8: R5.1 U1.E7 | length 375.9
  Top Layer w5: v1(-188.98,-125.98) U1.E7@-173.23,-110.24
  Top Layer w10: v1(-510,-94.49) R5.1@-510,-75
  MidLayer 3 w5: v1(-510,-94.49) -494.25,-110.24 -204.72,-110.24 v1(-188.98,-125.98)
CLK-24.5_3: R7.2 U5.59 | length 158.6
  Top Layer w5: R7.2@-1350,455 -1350,480 -1329.21,500.79 U5.59@-1225,500.79
CLK_7_N: R35.1 U1.M2 U2.K7 U3.K7 | length 1421.7
  Top Layer w4.7: v1(-167.76,-756.5) U2.K7@-152.01,-772.24 ; v1(31.5,-283.46) U1.M2@47.24,-267.72 ; v1(262.24,-756.5) U3.K7@277.99,-772.24
  MidLayer1 w4.7: v1(-167.76,-756.5) -131.26,-720 200.11,-720 225.86,-745.75 251.5,-745.75 v1(262.24,-756.5) 272.99,-745.75 300,-745.75 ccw(c300,-725.75) 320,-725.75 320,-699.75 ccw(c300,-699.75) 300,-679.75 254.75,-679.75 165,-590 -5,-590 cw(c-5,-580) -15,-580 -15,-387.09 cw(c-5,-387.09) -5,-377.09 11.5,-377.09 ccw(c11.5,-357.09) 31.5,-357.09 v1(31.5,-283.46)
  Bottom Layer w5: -236.5,-740 -184.26,-740 v1(-167.76,-756.5)
CLK_7_P: R35.2 U1.L2 U2.J7 U3.J7 | length 1446.6
  Top Layer w4.7: v1(-167.76,-725) U2.J7@-152.01,-740.75 ; v1(0,-283.46) U1.L2@15.75,-267.72 ; v1(262.24,-725) U3.J7@277.99,-740.75
  MidLayer1 w4.7: v1(-167.76,-725) -151.96,-725 -136.96,-710 204.25,-710 230,-735.75 251.5,-735.75 v1(262.24,-725) 272.99,-735.75 300,-735.75 ccw(c300,-725.75) 310,-725.75 310,-699.75 ccw(c300,-699.75) 300,-689.75 241.3,-689.75 238.3,-692.75 236.3,-694.75 cw(c230.64,-689.1) 224.98,-683.44 228.98,-679.45 ccw(c223.33,-673.78) 228.98,-668.12 218.98,-658.12 ccw(c213.33,-663.78) 207.67,-658.12 cw(c202.01,-652.47) 196.35,-646.81 ccw(c190.7,-641.15) 196.35,-635.5 160.86,-600 -5,-600 cw(c-5,-580) -25,-580 -25,-387.09 cw(c-5,-387.09) -5,-367.09 11.5,-367.09 ccw(c11.5,-357.09) 21.5,-357.09 21.5,-304.96 v1(0,-283.46)
  Bottom Layer w5: -236.5,-725 v1(-167.76,-725)
CLKE_7: U1.N3 U2.K9 U3.K9 | length 1524.5
  Top Layer w5.49: U2.K9@-89.02,-772.24 v1(-73.27,-756.5) ; U1.N3@78.74,-236.22 v1(94.49,-251.97) ; U3.K9@340.98,-772.24 v1(356.73,-787.99)
  MidLayer1 w5.49: v1(-73.27,-756.5) -57.52,-740.75 175.75,-740.75 207.25,-772.25 268.77,-772.25 340.99,-772.24 v1(356.73,-787.99)
  MidLayer2 w5.49: v1(94.49,-251.97) 110.24,-267.72 110.24,-435.73 ccw(c118.24,-435.73) 126.24,-435.73 126.24,-312 cw(c134.24,-312) 142.24,-312 142.24,-447.24 155,-460 155,-710 217.24,-772.24 340.98,-772.24 v1(356.73,-787.99)
D0: U1.C3 U2.F8 | length 510.4
  Top Layer w5.49: v1(-251.97,-251.97) U1.C3@-236.22,-236.22 ; U2.F8@-120.51,-646.26 v1(-104.76,-630.51)
  MidLayer2 w5.49: v1(-251.97,-251.97) -251.97,-308.03 -210,-350 -165,-350 -125,-390 -125,-610.27 v1(-104.76,-630.51)
D1: U1.B3 U2.H3 | length 507.9
  Top Layer w5.49: v1(-293.74,-693.5) U2.H3@-277.99,-709.25 ; v1(-283.46,-251.97) U1.B3@-267.72,-236.22
  MidLayer2 w5.49: v1(-293.74,-693.5) -309.49,-677.76 -309.49,-345.51 -315,-340 -315,-283.5 v1(-283.46,-251.97)
D2: U1.A2 U2.F2 | length 545.4
  Top Layer w5.49: U2.F2@-309.49,-646.26 -325.24,-630.51 -354.49,-630.51 -380,-605 -380,-382.23 cw(c-372,-382.23) -364,-382.23 -364,-407.23 ccw(c-356,-407.23) -348,-407.23 -348,-316.5 U1.A2@-299.21,-267.72
D3: U1.A4 U2.G2 | length 501.9
  Top Layer w5.49: v1(-340.98,-251.97) U1.A4@-299.21,-204.72 ; v1(-325.24,-662.01) U2.G2@-309.49,-677.76
  MidLayer2 w5.49: v1(-340.98,-251.97) -340.98,-646.26 v1(-325.24,-662.01)
D4: U1.D3 U2.E3 | length 526.4
  Top Layer w5.49: v1(-293.74,-599.02) U2.E3@-277.99,-614.76 ; v1(-220.47,-251.97) U1.D3@-204.72,-236.22
  MidLayer1 w5: -340.98,-567.58 cw(c-325.24,-567.52) -340.98,-567.52
  MidLayer1 w5.49: v1(-293.74,-599.02) -309.49,-583.27 -325.24,-583.27 cw(c-325.24,-567.52) -340.98,-567.58 -340.98,-280.98 -327.72,-267.72 -236.22,-267.72 v1(-220.47,-251.97)
D5: U1.D1 U2.H8 | length 557.4
  Top Layer w5.49: U1.D1@-204.72,-299.21 -204.72,-339.72 -215,-350 -215,-655 -207.99,-662.01 -185,-662.01 cw(c-185,-669.88) -185,-677.76 -207,-677.76 ccw(c-207,-685.63) -207,-693.5 -136.26,-693.5 U2.H8@-120.51,-709.25
D6: U1.C1 U2.H7 | length 512.1
  Top Layer w5.49: U1.C1@-236.22,-299.21 -236.22,-343.78 -230,-350 ; -230,-349.87 -230,-717.13 ccw(c-222.13,-717.13) -214.25,-717.13 cw(c-206.38,-717.13) -206.38,-709.25 U2.H7@-152.01,-709.25
D7: U1.E1 U2.F7 | length 543.4
  Top Layer w5.49: U1.E1@-173.23,-299.21 -173.23,-348.23 -190,-365 -190,-536.05 -163.14,-562.91 ccw(c-152.01,-551.77) -152.01,-567.52 cw(c-152.01,-583.27) -136.26,-583.27 -136.26,-614.76 cw(c-152.01,-614.76) -163.14,-625.9 -185,-604.04 -185,-590 ccw(c-192.87,-590) -200.75,-590 -200.75,-614.25 -168.74,-646.26 U2.F7@-152.01,-646.26
D8: U1.E2 U2.D7 | length 355.1
  Top Layer w5.49: U1.E2@-173.23,-267.72 -188.98,-283.46 -188.98,-343.98 -200,-355 -200,-550 -166.73,-583.27 U2.D7@-152.01,-583.27
D9: U1.E3 U2.A2 | length 328.3
  Top Layer w5.49: v1(-325.24,-473.03) U2.A2@-309.49,-488.78 ; v1(-188.98,-251.97) U1.E3@-173.23,-236.22
  MidLayer1 w5.49: v1(-325.24,-473.03) -325.24,-405.24 -245,-325 -245,-317.22 -231.61,-303.83 cw(c-220.47,-314.96) -220.47,-299.21 ccw(c-220.47,-283.46) -209.34,-294.6 -188.98,-274.24 v1(-188.98,-251.97)
D10: U1.G3 U2.C2 | length 428.7
  Top Layer w5.49: v1(-325.24,-536.02) U2.C2@-309.49,-551.77 ; v1(-125.98,-251.97) U1.G3@-110.24,-236.22
  MidLayer1 w5.49: v1(-325.24,-536.02) -309.49,-520.27 -309.49,-444.49 -290,-425 -260,-425 -190,-355 -190,-315.98 v1(-125.98,-251.97)
D11: U1.H3 U2.A3 | length 440.5
  Top Layer w5.49: v1(-293.74,-473.03) U2.A3@-277.99,-488.78 ; v1(-94.49,-251.97) U1.H3@-78.74,-236.22
  MidLayer1 w5.49: v1(-293.74,-473.03) -255,-473.03 ccw(c-255,-465.03) -255,-457.03 -275,-457.03 cw(c-275,-449.03) -275,-441.03 -251.03,-441.03 -175,-365 -175,-316.99 -148.01,-290 -132.52,-290 v1(-94.49,-251.97)
D12: U1.J3 U2.C3 | length 441.3
  Top Layer w5.49: v1(-293.74,-536.02) U2.C3@-277.99,-551.77 ; v1(-62.99,-251.97) U1.J3@-47.24,-236.22
  MidLayer1 w5.49: v1(-293.74,-536.02) -157.48,-399.76 -157.48,-321.48 cw(c-141.73,-321.48) -141.73,-305.74 -116.76,-305.74 v1(-62.99,-251.97)
D13: U1.H2 U2.A7 | length 449.5
  Top Layer w5.49: U2.A7@-152.01,-488.78 -110,-446.77 -110,-355 cw(c-102,-355) -94,-355 -94,-428.73 ccw(c-86,-428.73) -78,-428.73 -78,-327 -94.49,-310.51 -94.49,-283.46 U1.H2@-78.74,-267.72
D14: U1.H1 U2.B8 | length 434.2
  Top Layer w5.49: U2.B8@-120.51,-520.28 -104.76,-504.53 -75,-504.53 -56.5,-486.03 -56.5,-418.77 cw(c-48.5,-418.77) -40.5,-418.77 -40.5,-467.5 ccw(c-32.5,-467.5) -24.5,-467.5 -24.5,-418.77 ccw(c-48.5,-418.77) -31.53,-401.8 -62,-371.33 -62,-315.95 U1.H1@-78.74,-299.21
D15: U1.J1 U2.C8 | length 451.4
  Top Layer w5.49: U2.C8@-120.51,-551.77 -104.76,-536.02 -41.48,-536.02 -23.5,-554 -23.5,-576 ccw(c-15.5,-576) -7.5,-576 -7.5,-397.5 -47.24,-357.76 U1.J1@-47.24,-299.21
D16: U1.P1 U3.A2 | length 438.6
  Top Layer w5.49: U1.P1@110.24,-299.21 110.24,-353 cw(c102.24,-353) 102.24,-361 76.24,-361 ccw(c76.24,-369) 76.24,-377 102.24,-377 cw(c102.24,-385) 102.24,-393 36.27,-393 ccw(c36.27,-417) 36.27,-441 112.51,-441 cw(c112.51,-449) 120.51,-449 U3.A2@120.51,-488.78
D17: U1.P3 U3.C2 | length 396.4
  Top Layer w5.49: v1(104.76,-536.02) U3.C2@120.51,-551.77 ; U1.P3@110.24,-236.22 v1(125.98,-251.97)
  MidLayer1 w5.49: v1(104.76,-536.02) 89.02,-520.27 89.02,-350.55 cw(c97.02,-350.55) 105.02,-350.55 ccw(c113.02,-350.55) 121.02,-350.55 121.02,-310.54 110.24,-299.76 110.24,-267.72 v1(125.98,-251.97)
D18: U1.R3 U3.C3 | length 477.1
  Top Layer w5.49: v1(136.26,-536.02) U3.C3@152.01,-551.77 ; U1.R3@141.73,-236.22 v1(157.48,-251.97)
  MidLayer1 w5.49: v1(136.26,-536.02) 120.51,-520.27 120.51,-485.51 109.73,-474.73 109.73,-419.64 cw(c117.73,-419.64) 125.73,-419.64 125.73,-460 ccw(c133.73,-460) 141.73,-460 141.73,-267.72 v1(157.48,-251.97)
D19: U1.R1 U3.A3 | length 403.8
  Top Layer w5.49: U1.R1@141.73,-299.21 125.98,-314.96 125.98,-401 cw(c117.98,-401) 117.98,-409 36.27,-409 ccw(c36.27,-417) 36.27,-425 144.01,-425 cw(c144.01,-433) 152.01,-433 U3.A3@152.01,-488.78
D20: U1.T4 U3.D7 | length 436.6
  Top Layer w5.49: U1.T4@173.23,-204.72 v1(188.98,-220.47) ; v1(262.24,-567.52) U3.D7@277.99,-583.27
  MidLayer1 w5.49: v1(188.98,-220.47) 204.72,-236.22 204.72,-289.72 280,-365 280,-549.76 v1(262.24,-567.52)
D21: U1.U4 U3.B8 | length 372
  Top Layer w5.49: U1.U4@204.72,-204.72 v1(220.47,-220.47) ; U3.B8@309.49,-520.28 v1(325.24,-504.53)
  MidLayer1 w5.49: v1(220.47,-220.47) 236.22,-236.22 236.22,-267.72 309.49,-340.98 309.49,-488.78 v1(325.24,-504.53)
D22: U1.U2 U3.A7 | length 351.5
  Top Layer w5.49: v1(204.72,-348.99) 220.47,-333.24 220.47,-283.46 U1.U2@204.72,-267.72 ; v1(262.24,-473.03) U3.A7@277.99,-488.78
  MidLayer1 w5.49: v1(204.72,-348.99) 230.24,-374.51 230.24,-425 ccw(c238.24,-425) 246.24,-425 246.24,-400 cw(c254.24,-400) 262.24,-400 v1(262.24,-473.03)
D23: U1.U3 U3.C8 | length 372
  Top Layer w5.49: U1.U3@204.72,-236.22 v1(220.47,-251.97) ; U3.C8@309.49,-551.77 v1(325.24,-536.02)
  MidLayer1 w5.49: v1(220.47,-251.97) 220.47,-280.47 295,-355 295,-505.79 v1(325.24,-536.02)
D24: U1.V1 U3.E3 | length 617.4
  Top Layer w5.49: U3.E3@152.01,-614.76 184.22,-582.55 184.22,-375 cw(c192.22,-375) 200.22,-375 200.22,-490 ccw(c208.22,-490) 216.22,-490 216.22,-368.78 236.22,-348.78 U1.V1@236.22,-299.21
D25: U1.Y3 U3.H7 | length 605.5
  Top Layer w5.49: v1(262.24,-662.01) 262.24,-693.5 U3.H7@277.99,-709.25 ; U1.Y3@299.21,-236.22 v1(321.48,-236.22)
  MidLayer1 w5.49: v1(262.24,-662.01) 277.99,-646.26 340.98,-646.26 372.48,-614.76 372.48,-287.22 v1(321.48,-236.22)
D26: U1.W1 U3.G2 | length 570.7
  Top Layer w5.49: U3.G2@120.51,-677.76 136.26,-662.01 205.78,-662.01 cw(c205.78,-677.76) 221.52,-677.7 221.52,-692.7 ccw(c233.02,-692.7) 244.52,-692.7 244.52,-465.48 267.72,-442.28 U1.W1@267.72,-299.21
D27: U1.Y4 U3.H8 | length 615.9
  Top Layer w5.49: U1.Y4@299.21,-204.72 321.97,-204.72 390,-272.76 390,-675 371.5,-693.5 325.24,-693.5 U3.H8@309.49,-709.25
D28: U1.Y2 U3.H3 | length 528.6
  Top Layer w5.49: U3.H3@152.01,-709.25 174.28,-709.25 v1(205.78,-677.76) ; U1.Y2@299.21,-267.72 v1(314.96,-283.46)
  MidLayer 3 w5.49: v1(205.78,-677.76) 205.78,-392.65 v1(314.96,-283.46)
D29: U1.W3 U3.F8 | length 602.5
  Top Layer w5.49: U1.W3@267.72,-236.22 283.46,-251.97 311.97,-251.97 343,-283 343,-425 ccw(c351,-425) 359,-425 359,-400 cw(c367,-400) 375,-400 375,-610 354.49,-630.51 325.24,-630.51 U3.F8@309.49,-646.26
D30: U1.V2 U3.F2 | length 607.7
  Top Layer w5.49: U3.F2@120.51,-646.26 136.26,-630.51 189.49,-630.51 198,-622 198,-580 cw(c206,-580) 214,-580 214,-630 ccw(c222,-630) 230,-630 230,-460 251.97,-438.03 251.97,-283.46 U1.V2@236.22,-267.72
D31: U1.V3 U3.F7 | length 659.1
  Top Layer w5.49: U1.V3@236.22,-236.22 v1(251.97,-251.97) ; U3.F7@277.99,-646.26 v1(293.74,-630.51)
  MidLayer1 w5.49: v1(251.97,-251.97) 311.97,-251.97 340.98,-280.98 340.98,-567.52 cw(c325.24,-567.52) 325.29,-583.27 241.73,-583.27 ccw(c241.73,-603.27) 227.59,-617.41 240.69,-630.51 v1(293.74,-630.51)
DM0_7: U1.A1 U2.E7 | length 481
  Top Layer w5.49: v1(-299.21,-321.48) U1.A1@-299.21,-299.21 ; v1(-167.76,-599.02) U2.E7@-152.01,-614.76
  MidLayer2 w5.49: v1(-299.21,-321.48) -199.76,-420.94 -199.76,-486.67 ccw(c-191.76,-486.67) -183.76,-486.67 -183.76,-452.94 cw(c-175.76,-452.94) -167.76,-452.94 v1(-167.76,-599.02)
DM1_7: U1.F1 U2.D3 | length 445.6
  Top Layer w5.49: v1(-293.74,-567.52) U2.D3@-277.99,-583.27 ; v1(-141.73,-321.48) U1.F1@-141.73,-299.21
  MidLayer1 w5.49: v1(-293.74,-567.52) -240,-567.52 ccw(c-240,-559.52) -240,-551.52 -260,-551.52 cw(c-260,-543.52) -260,-535.52 -236.03,-535.52 -141.73,-441.22 v1(-141.73,-321.48)
DM2_7: U1.T1 U3.D3 | length 406.4
  Top Layer w5.49: U3.D3@152.01,-583.27 173.23,-562.05 173.23,-341.77 ccw(c165.23,-341.77) 157.23,-341.77 157.23,-366.77 cw(c149.23,-366.77) 141.23,-366.77 141.23,-331.21 U1.T1@173.23,-299.21
DM3_7: U1.Y1 U3.E7 | length 603.3
  Top Layer w5.49: U3.E7@277.99,-614.76 293.74,-599.02 293.74,-471.12 282.96,-460.34 282.96,-331 cw(c290.96,-331) 298.96,-331 298.96,-441 ccw(c306.96,-441) 314.96,-441 314.96,-314.96 U1.Y1@299.21,-299.21
DONE_8: Q4.2 R52.2 U1.R11 | length 2385.8
  Top Layer w5: U1.R11@141.73,15.75 v1(157.48,31.5)
  Top Layer w12: v1@-850,1060 Q4.2@-850,1086
  MidLayer1 w5: v1(157.48,31.5) 141.73,47.24 125.98,47.24 cw(c125.98,62.99) 110.24,62.99 110.24,325.24 345,560 361,560 v1(383,582)
  MidLayer 3 w5: v1(-849,1060) -705,1060 -700,1065 -445,1065 -385,1005 -385,752.5 -152.5,520 -20,520 25,565 366,565 v1(383,582)
DQS0_7_N: U1.B2 U2.G3 | length 479.8
  Top Layer w4.7: U2.G3@-277.99,-677.76 -293.74,-662.01 -293.74,-646.26 cw(c-277.99,-646.26) -277.99,-630.51 ccw(c-277.99,-614.49) -261.97,-614.49 -261.97,-450 ccw(c-269.97,-450) -269.97,-442 cw(c-269.97,-424) -269.97,-406 ccw(c-269.97,-398) -261.97,-398 -261.97,-358.03 -283.46,-336.54 -283.46,-283.46 U1.B2@-267.72,-267.72
DQS0_7_P: U1.C2 U2.F3 | length 500.1
  Top Layer w4.7: U2.F3@-277.99,-646.26 -260,-664.25 -260,-671 ccw(c-252,-671) -244,-671 -244,-656.28 -251.97,-648.31 -251.97,-450 ccw(c-269.97,-450) -269.97,-432 cw(c-269.97,-424) -269.97,-416 ccw(c-269.97,-398) -251.97,-398 -251.97,-283.46 U1.C2@-236.22,-267.72
DQS1_7_N: U1.F2 U2.B7 | length 361.6
  Top Layer w4.7: U2.B7@-152.01,-520.28 -166.78,-509.87 cw(c-152.01,-488.78) -177.76,-488.78 -177.76,-455.08 -138.33,-415.66 ccw(c-143.98,-410) -143.98,-402 -158.98,-402 cw(c-158.98,-384) -158.98,-366 -143.98,-366 ccw(c-143.98,-358) -143.98,-350 -149.48,-350 cw(c-149.48,-342) -157.48,-342 -157.48,-283.46 U1.F2@-141.73,-267.72
DQS1_7_P: U1.G2 U2.C7 | length 391.3
  Top Layer w4.7: U2.C7@-152.01,-551.77 -136.26,-536.02 -136.26,-520.28 ccw(c-152.01,-520.28) -152.01,-504.53 cw(c-152.01,-488.78) -167.76,-488.78 -167.76,-459.23 -131.26,-422.73 ccw(c-143.98,-410) -143.98,-392 -158.98,-392 cw(c-158.98,-384) -158.98,-376 -143.98,-376 ccw(c-143.98,-358) -125.98,-358 -125.98,-283.46 U1.G2@-110.24,-267.72
DQS2_7_N: U1.T2 U3.B7 | length 382.9
  Top Layer w4.7: U1.T2@173.23,-267.72 v1(188.98,-283.46) ; v1(262.24,-504.53) U3.B7@277.99,-520.28
  MidLayer1 w4.7: v1(188.98,-283.46) 178.23,-294.21 178.23,-393 ccw(c186.23,-393) 186.23,-401 189,-401 cw(c189,-409) 189,-417 186.23,-417 ccw(c186.23,-425) 178.23,-425 178.23,-497.87 195.64,-515.27 251.5,-515.27 v1(262.24,-504.53)
DQS2_7_P: U1.R2 U3.C7 | length 375.6
  Top Layer w4.7: U1.R2@141.73,-267.72 v1(157.48,-283.46) ; v1(262.24,-536.02) U3.C7@277.99,-551.77
  MidLayer1 w4.7: v1(157.48,-283.46) 168.23,-294.21 168.23,-502.01 191.5,-525.28 251.5,-525.28 v1(262.24,-536.02)
DQS3_7_N: U1.W4 U3.G3 | length 560
  Top Layer w4.7: U3.G3@152.01,-677.76 v1(174.28,-677.76) ; U1.W4@267.72,-204.72 v1(283.46,-220.47)
  MidLayer2 w4.7: v1(174.28,-677.76) 190.03,-662.01 212.25,-661.89 225,-649.14 225,-475 265,-435 265,-279.66 283.46,-261.2 v1(283.46,-220.47)
DQS3_7_P: U1.W5 U3.F3 | length 576
  Top Layer w4.7: U3.F3@152.01,-646.26 v1(174.28,-646.26) ; U1.W5@267.72,-173.23 v1(283.47,-188.98)
  MidLayer2 w4.7: v1(174.28,-646.26) 175.54,-645 190,-645 197.01,-652.01 207.99,-652.01 215,-645 215,-470 255,-430 255,-272.72 267.72,-260 267.72,-204.72 v1(283.47,-188.98)
e1-/IRQ: U1.R16 U10.31 | length 942.6
  Top Layer w5: v1(125.98,157.48) U1.R16@141.73,173.23 ; U10.31@907,254.13 931.13,254.13 935.13,258.13 v1(955,258.13)
  MidLayer1 w5: v1(125.98,157.48) 141.73,173.23 578.23,173.23 663.13,258.13 v1(955,258.13)
e1-/RESET: R58.1 U1.P20 U10.12 | length 827.8
  Top Layer w5: U1.P20@110,299.45 110,340 210,440 295,440 325,470 325,521 R58.1@321,525 ; R58.1@320,526 R58.1@321,525 ; U10.12@713,380.12 674.88,380.12 520,535 390,535 380,525 R58.1@321,525
e1-CLK25_5: R38.2 U10.37 | length 733.7
  Top Layer w6: U10.37@907,348.62 926.38,348.62 939.27,335.73 939.27,323.73 v1(940,323)
  Top Layer w18: R38.2@1461,35 v1(1461,53)
  MidLayer 3 w5: v1(940,323) 1093,323 1110,340 1205,340 1461,84 v1(1461,53)
e1-LED1_5: J8.11A R69.2 U10.33 | length 2277.7
  Top Layer w5: U10.33@907,285.63 930.61,285.63 v1(940,279.76)
  Top Layer w18: v1(1081,393.5) R69.2@1081,413
  MidLayer1 w10: v1(940,279.76) 984.76,279.76 1080,375 v1@1080,395.5 ; J8.11A@1035,1090 1630,1090 1705,1015 1705,580 1655,530 1217.5,530 v1(1081,393.5)
  Bottom Layer w10: 1063.19,1100.22 1035,1120 ccw(c1035,1090) 1063.19,1100.26
e1-LED2_5: J8.14A R68.2 U10.34 | length 1623.2
  Top Layer w5: U10.34@907,301.38 v1(955,301.38)
  Top Layer w18: v1(1045,393.5) R68.2@1045,413
  MidLayer1 w10: J8.14A@525,1160 475,1160 370,1055 370,700 540,530 985,530 1045,470 v1(1045,393.5) 1045,370 1000,325 972.97,325 967.3,319.34 959,311.03 ; v1@952.17,304.21 959,311.03 ; v1(955,301.38) v1@955,303.54 ; v1@959,301.38 959,311.03
e1-MDIO-C: U1.R19 U9.3 | length 384.1
  Top Layer w5: U1.R19@141.73,267.72 157.48,283.46 157.48,347.48 220,410 315,410 359.41,454.41 U9.3@411,454.41
e1-MDIO-C/1.8_5: U9.4 U10.13 | length 261.3
  Top Layer w5: U9.4@489,454.41 545.59,454.41 635.63,364.37 U10.13@713,364.37
e1-MDIO-D: U1.T20 U8.4 | length 303.8
  Top Layer w5: U1.T20@173.23,299.21 173.23,333.23 237,397 367,397 380.59,410.59 U8.4@411,410.59
e1-MDIO-D/1.8_5: R62.1 U8.3 U10.14 | length 249.7
  Top Layer w5: U8.3@489,410.59 539.41,410.59 R62.1@545,405 570,405 626.38,348.62 U10.14@713,348.62
e1-RxCLK_5: R3.1 U1.Y7 | length 641.2
  Top Layer w5: U1.Y7@299.21,-110.24 389.76,-110.24 535,35 780,35 824,79 R3.1@824,117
